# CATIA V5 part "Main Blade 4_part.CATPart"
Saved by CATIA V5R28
Part number: Main Blade 4_part
Definition: design
Nomenclature: Main Blade 4_part
Source: Unknown
Bounding box of the stored display mesh (mm): x -2.545 to 9.895, y 1.92 to 5.169, z 1.529 to 7.748
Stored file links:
  D:\paraturbo-cad\STEP\Turbocompressor_for_Christophe\Main Blade 4_part.CATPart
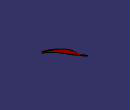
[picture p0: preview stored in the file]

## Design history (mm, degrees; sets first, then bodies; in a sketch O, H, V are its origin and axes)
Body1 "MANIFOLD_SOLID_BREP #40595" (main body)
  Solid1: solid without history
